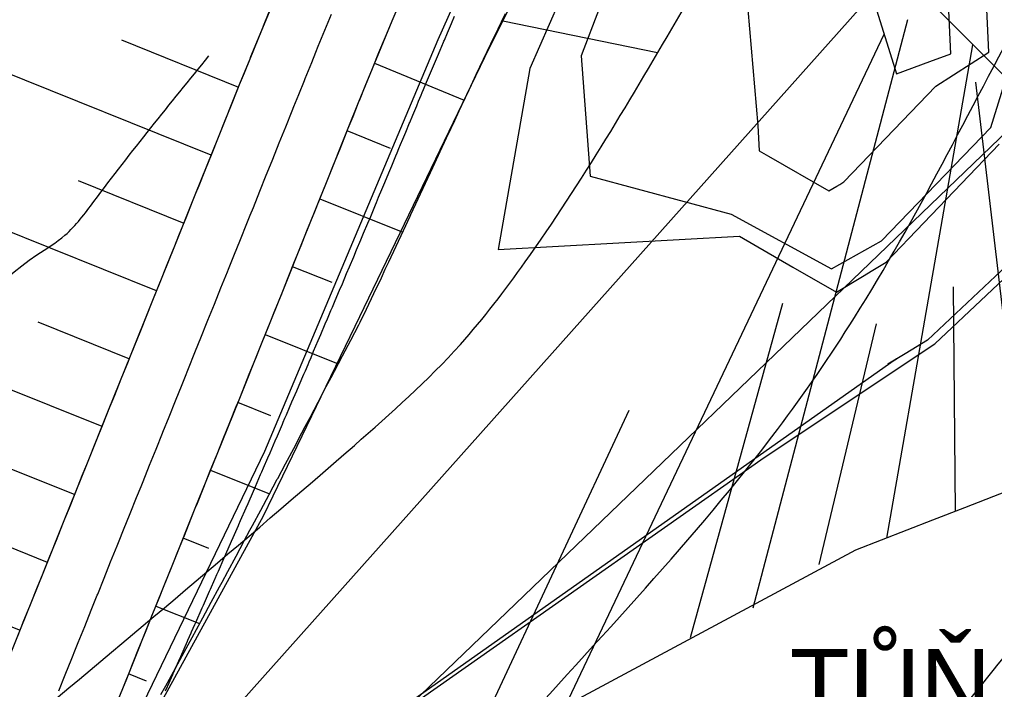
# Model space of a CAD drawing. Extents: x -564091 to -563943, y -1163604 to -1163394.
# Drawn here: x -563977.47 to -563960.81, y -1163497.05 to -1163485.61 of the extents above; entities that cross this region are included whole.
import ezdxf

# ---------------------------------------------------------------- set-up
doc = ezdxf.new("R2010")
doc.units = 0
for name, color, linetype in [('4', 7, 'Continuous'), ('5', 7, 'Continuous'), ('Default', 7, 'Continuous'), ('Line', 7, 'Continuous'), ('Vrstva 24', 7, 'Continuous'), ('Vrstva 25', 7, 'Continuous'), ('Vrstva 26', 7, 'Continuous')]:
    doc.layers.add(name, color=color, linetype=linetype)

msp = doc.modelspace()

# ---------------------------------------------------------------- linework, layer by layer
for points in [[(-563976.663, -1163501.462), (-563964.742, -1163493.091), (-563961.829, -1163491.15), (-563957.41, -1163486.988), (-563956.735, -1163486.627), (-563953.281, -1163481.221), (-563953.993, -1163478.343), (-563957.796, -1163470.824), (-563957.81, -1163470.439), (-563957.835, -1163469.754), (-563958.239, -1163469.063), (-563958.187, -1163468.683), (-563959.529, -1163466.077), (-563960.166, -1163464.984), (-563964.31, -1163473.527), (-563966.903, -1163478.544), (-563968.406, -1163481.669), (-563970.316, -1163485.955), (-563973.278, -1163492.988), (-563976.735, -1163500.155), (-563977.161, -1163500.889), (-563977.363, -1163501.307)], [(-563962.125, -1163475.875), (-563962.765, -1163475.108), (-563963.856, -1163475.351), (-563965.212, -1163477.785), (-563966.919, -1163483.486), (-563967.557, -1163485.407), (-563967.871, -1163486.226), (-563967.716, -1163488.285), (-563965.306, -1163488.933), (-563963.594, -1163489.868), (-563962.736, -1163489.387), (-563960.869, -1163487.453), (-563959.333, -1163482.497), (-563959.613, -1163479.666)], [(-563962.48, -1163486.536), (-563961.911, -1163486.326), (-563961.553, -1163486.194), (-563961.747, -1163482.024), (-563961.878, -1163479.201), (-563962.246, -1163479.103), (-563962.794, -1163479.244), (-563962.818, -1163479.245), (-563963.128, -1163481.546), (-563962.901, -1163485.181)]]:
    msp.add_lwpolyline(points, close=True)
for points in [[(-563960.523, -1163486.688), (-563961.829, -1163485.385), (-563962.324, -1163483.708), (-563962.461, -1163482.584), (-563962.597, -1163481.459), (-563962.579, -1163480.501), (-563961.736, -1163479.195), (-563961.088, -1163479.165), (-563960.669, -1163479.145), (-563960.089, -1163479.118), (-563959.09, -1163479.072), (-563958.091, -1163479.026), (-563957.266, -1163478.987), (-563957.092, -1163478.979), (-563955.995, -1163480.274), (-563955.699, -1163482.25), (-563955.954, -1163483.392), (-563956.177, -1163485.128), (-563956.177, -1163485.128), (-563956.177, -1163485.128), (-563957.55, -1163486.21)], [(-563965.051, -1163485.101), (-563964.85, -1163487.418), (-563964.83, -1163487.847), (-563964.668, -1163487.941), (-563963.636, -1163488.535), (-563963.502, -1163488.454), (-563963.449, -1163488.423), (-563963.381, -1163488.382), (-563961.809, -1163486.742), (-563960.902, -1163486.164), (-563961.157, -1163480.663)], [(-563960.591, -1163493.664), (-563961.319, -1163493.948), (-563961.866, -1163494.161), (-563963.182, -1163494.674), (-563968.138, -1163497.33), (-563968.634, -1163497.596), (-563970.944, -1163498.688), (-563971.597, -1163498.997), (-563976.56, -1163501.343), (-563977.332, -1163501.295), (-563976.988, -1163500.693), (-563975.559, -1163498.192), (-563975.396, -1163497.906), (-563973.296, -1163494.084), (-563973.133, -1163493.747), (-563971.654, -1163490.682), (-563969.513, -1163486.248), (-563968.702, -1163484.611)], [(-563977.812, -1163496.922), (-563977.438, -1163495.994), (-563977.065, -1163495.066), (-563976.691, -1163494.139), (-563976.318, -1163493.211), (-563975.945, -1163492.283), (-563975.571, -1163491.355), (-563975.198, -1163490.428), (-563974.825, -1163489.5), (-563974.451, -1163488.572), (-563974.078, -1163487.645), (-563973.705, -1163486.717), (-563973.527, -1163486.276), (-563973.328, -1163485.785), (-563972.941, -1163484.852)], [(-563977.421, -1163501.309), (-563977.076, -1163500.451), (-563977.017, -1163500.304), (-563976.703, -1163499.524), (-563976.33, -1163498.596), (-563975.956, -1163497.668), (-563975.583, -1163496.741), (-563975.209, -1163495.813), (-563974.836, -1163494.885), (-563974.463, -1163493.958), (-563974.089, -1163493.03), (-563973.716, -1163492.102), (-563973.343, -1163491.175), (-563972.969, -1163490.247), (-563972.596, -1163489.319), (-563972.223, -1163488.391), (-563971.849, -1163487.464), (-563971.672, -1163487.023), (-563971.476, -1163486.542), (-563971.097, -1163485.627), (-563970.817, -1163484.966)], [(-563968.084, -1163484.934), (-563968.744, -1163486.445), (-563969.289, -1163489.534), (-563965.164, -1163489.309), (-563965.164, -1163489.309), (-563964.25, -1163489.835), (-563963.508, -1163490.263), (-563963.061, -1163489.994), (-563962.883, -1163489.889), (-563962.657, -1163489.751), (-563960.727, -1163487.738)], [(-563977.502, -1163496.152), (-563977.438, -1163495.994), (-563977.391, -1163495.877), (-563977.28, -1163495.601), (-563977.169, -1163495.326), (-563977.065, -1163495.066), (-563977.059, -1163495.051), (-563976.948, -1163494.775), (-563976.837, -1163494.5), (-563976.726, -1163494.225), (-563976.691, -1163494.139), (-563976.615, -1163493.949), (-563976.505, -1163493.674), (-563976.394, -1163493.399), (-563976.318, -1163493.211), (-563976.283, -1163493.123), (-563976.172, -1163492.848), (-563976.061, -1163492.573), (-563975.95, -1163492.297), (-563975.945, -1163492.283), (-563975.84, -1163492.022), (-563975.729, -1163491.747), (-563975.618, -1163491.471), (-563975.571, -1163491.355), (-563975.507, -1163491.196), (-563975.396, -1163490.921), (-563975.286, -1163490.645), (-563975.198, -1163490.428), (-563975.175, -1163490.37), (-563975.064, -1163490.095), (-563974.953, -1163489.819), (-563974.842, -1163489.544), (-563974.825, -1163489.5), (-563974.732, -1163489.269), (-563974.621, -1163488.994), (-563974.51, -1163488.718), (-563974.451, -1163488.572), (-563974.399, -1163488.443), (-563974.288, -1163488.168), (-563974.177, -1163487.892), (-563974.078, -1163487.645), (-563974.067, -1163487.617), (-563973.956, -1163487.342), (-563973.845, -1163487.066), (-563973.734, -1163486.791), (-563973.705, -1163486.717), (-563973.623, -1163486.516), (-563973.527, -1163486.276), (-563973.512, -1163486.24), (-563973.4, -1163485.962), (-563973.328, -1163485.785), (-563973.287, -1163485.685), (-563973.173, -1163485.407)], [(-563975.757, -1163497.174), (-563975.646, -1163496.899), (-563975.583, -1163496.741), (-563975.536, -1163496.623), (-563975.425, -1163496.348), (-563975.314, -1163496.073), (-563975.209, -1163495.813), (-563975.203, -1163495.797), (-563975.092, -1163495.522), (-563974.982, -1163495.247), (-563974.871, -1163494.971), (-563974.836, -1163494.885), (-563974.76, -1163494.696), (-563974.649, -1163494.421), (-563974.538, -1163494.145), (-563974.463, -1163493.958), (-563974.428, -1163493.87), (-563974.317, -1163493.595), (-563974.206, -1163493.319), (-563974.095, -1163493.044), (-563974.089, -1163493.03), (-563973.984, -1163492.769), (-563973.873, -1163492.493), (-563973.763, -1163492.218), (-563973.716, -1163492.102), (-563973.652, -1163491.943), (-563973.541, -1163491.668), (-563973.43, -1163491.392), (-563973.343, -1163491.175), (-563973.319, -1163491.117), (-563973.209, -1163490.842), (-563973.098, -1163490.566), (-563972.987, -1163490.291), (-563972.969, -1163490.247), (-563972.876, -1163490.016), (-563972.765, -1163489.74), (-563972.655, -1163489.465), (-563972.596, -1163489.319), (-563972.544, -1163489.19), (-563972.433, -1163488.914), (-563972.322, -1163488.639), (-563972.223, -1163488.391), (-563972.211, -1163488.364), (-563972.101, -1163488.088), (-563971.99, -1163487.813), (-563971.879, -1163487.538), (-563971.849, -1163487.464), (-563971.768, -1163487.262), (-563971.672, -1163487.023), (-563971.657, -1163486.987), (-563971.547, -1163486.715), (-563971.476, -1163486.542), (-563971.436, -1163486.443), (-563971.324, -1163486.171), (-563971.212, -1163485.9), (-563971.098, -1163485.629), (-563971.097, -1163485.627), (-563970.984, -1163485.358)], [(-563976.796, -1163497.076), (-563976.685, -1163496.801), (-563976.574, -1163496.525), (-563976.511, -1163496.367), (-563976.463, -1163496.25), (-563976.353, -1163495.975), (-563976.242, -1163495.699), (-563976.137, -1163495.44), (-563976.131, -1163495.424), (-563976.02, -1163495.149), (-563975.909, -1163494.873), (-563975.798, -1163494.598), (-563975.764, -1163494.512), (-563975.688, -1163494.323), (-563975.577, -1163494.047), (-563975.466, -1163493.772), (-563975.39, -1163493.584), (-563975.355, -1163493.497), (-563975.244, -1163493.221), (-563975.134, -1163492.946), (-563975.023, -1163492.671), (-563975.017, -1163492.657), (-563974.912, -1163492.395), (-563974.801, -1163492.12), (-563974.69, -1163491.845), (-563974.644, -1163491.729), (-563974.58, -1163491.569), (-563974.469, -1163491.294), (-563974.358, -1163491.019), (-563974.27, -1163490.801), (-563974.247, -1163490.744), (-563974.136, -1163490.468), (-563974.025, -1163490.193), (-563973.915, -1163489.918), (-563973.897, -1163489.873), (-563973.804, -1163489.642), (-563973.693, -1163489.367), (-563973.582, -1163489.092), (-563973.524, -1163488.946), (-563973.471, -1163488.816), (-563973.361, -1163488.541), (-563973.25, -1163488.266), (-563973.15, -1163488.018), (-563973.139, -1163487.99), (-563973.028, -1163487.715), (-563972.917, -1163487.44), (-563972.807, -1163487.164), (-563972.777, -1163487.09), (-563972.696, -1163486.889), (-563972.599, -1163486.649), (-563972.585, -1163486.614), (-563972.474, -1163486.339), (-563972.402, -1163486.163), (-563972.361, -1163486.064), (-563972.249, -1163485.789), (-563972.135, -1163485.515)], [(-563975.049, -1163497.139), (-563974.967, -1163496.989), (-563974.906, -1163496.877), (-563974.763, -1163496.614), (-563974.62, -1163496.352), (-563974.485, -1163496.104), (-563974.477, -1163496.09), (-563974.335, -1163495.827), (-563974.192, -1163495.564), (-563974.05, -1163495.302), (-563974.006, -1163495.219), (-563973.909, -1163495.039), (-563973.767, -1163494.776), (-563973.625, -1163494.513), (-563973.529, -1163494.333), (-563973.484, -1163494.25), (-563973.343, -1163493.987), (-563973.202, -1163493.723), (-563973.062, -1163493.46), (-563973.055, -1163493.446), (-563972.922, -1163493.196), (-563972.782, -1163492.933), (-563972.642, -1163492.669), (-563972.583, -1163492.558), (-563972.502, -1163492.405), (-563972.363, -1163492.142), (-563972.224, -1163491.878), (-563972.114, -1163491.669), (-563972.085, -1163491.614), (-563971.946, -1163491.35), (-563971.808, -1163491.085), (-563971.669, -1163490.821), (-563971.647, -1163490.779), (-563971.537, -1163490.555), (-563971.41, -1163490.286), (-563971.283, -1163490.017), (-563971.216, -1163489.874), (-563971.157, -1163489.748), (-563971.03, -1163489.479), (-563970.904, -1163489.21), (-563970.791, -1163488.968), (-563970.778, -1163488.94), (-563970.653, -1163488.671), (-563970.527, -1163488.402), (-563970.402, -1163488.132), (-563970.368, -1163488.06), (-563970.277, -1163487.863), (-563970.168, -1163487.628), (-563970.152, -1163487.594), (-563970.03, -1163487.332), (-563969.952, -1163487.164), (-563969.908, -1163487.069), (-563969.785, -1163486.808), (-563969.662, -1163486.546), (-563969.538, -1163486.285), (-563969.537, -1163486.283), (-563969.414, -1163486.024), (-563969.289, -1163485.763), (-563969.233, -1163485.646), (-563969.164, -1163485.502)], [(-563975.049, -1163497.139), (-563974.967, -1163496.989), (-563974.906, -1163496.877), (-563974.763, -1163496.614), (-563974.62, -1163496.352), (-563974.485, -1163496.104), (-563974.477, -1163496.09), (-563974.335, -1163495.827), (-563974.192, -1163495.564), (-563974.05, -1163495.302), (-563974.006, -1163495.219), (-563973.909, -1163495.039), (-563973.767, -1163494.776), (-563973.625, -1163494.513), (-563973.529, -1163494.333), (-563973.484, -1163494.25), (-563973.343, -1163493.987), (-563973.202, -1163493.723), (-563973.062, -1163493.46), (-563973.055, -1163493.446), (-563972.922, -1163493.196), (-563972.782, -1163492.933), (-563972.642, -1163492.669), (-563972.583, -1163492.558), (-563972.502, -1163492.405), (-563972.363, -1163492.142), (-563972.224, -1163491.878), (-563972.114, -1163491.669), (-563972.085, -1163491.614), (-563971.946, -1163491.35), (-563971.808, -1163491.085), (-563971.669, -1163490.821), (-563971.647, -1163490.779), (-563971.537, -1163490.555), (-563971.41, -1163490.286), (-563971.283, -1163490.017), (-563971.216, -1163489.874), (-563971.157, -1163489.748), (-563971.03, -1163489.479), (-563970.904, -1163489.21), (-563970.791, -1163488.968), (-563970.778, -1163488.94), (-563970.653, -1163488.671), (-563970.527, -1163488.402), (-563970.402, -1163488.132), (-563970.368, -1163488.06), (-563970.277, -1163487.863), (-563970.168, -1163487.628), (-563970.152, -1163487.594), (-563970.03, -1163487.332), (-563969.952, -1163487.164), (-563969.908, -1163487.069), (-563969.785, -1163486.808), (-563969.662, -1163486.546), (-563969.538, -1163486.285), (-563969.537, -1163486.283), (-563969.414, -1163486.024), (-563969.289, -1163485.763), (-563969.233, -1163485.646), (-563969.164, -1163485.502)]]:
    msp.add_lwpolyline(points)
at = {"layer": '5'}
msp.add_line((-563974.94, -1163501.303), (-563959.546, -1163486.507), dxfattribs=at)
at = {"layer": 'Default'}
for points in [[(-563974.974, -1163497.079), (-563974.939, -1163497), (-563974.935, -1163496.992), (-563974.849, -1163496.797), (-563974.841, -1163496.78), (-563974.722, -1163496.513), (-563974.711, -1163496.488), (-563974.596, -1163496.229), (-563974.589, -1163496.212), (-563974.532, -1163496.085), (-563974.525, -1163496.068), (-563974.47, -1163495.944), (-563974.453, -1163495.906), (-563974.344, -1163495.659), (-563974.324, -1163495.615), (-563974.218, -1163495.374), (-563974.203, -1163495.339), (-563974.128, -1163495.17), (-563974.122, -1163495.155), (-563974.093, -1163495.09), (-563974.069, -1163495.034), (-563973.968, -1163494.805), (-563973.941, -1163494.744), (-563973.843, -1163494.52), (-563973.816, -1163494.459), (-563973.727, -1163494.254), (-563973.725, -1163494.249), (-563973.718, -1163494.234), (-563973.688, -1163494.165), (-563973.594, -1163493.949), (-563973.562, -1163493.876), (-563973.47, -1163493.664), (-563973.436, -1163493.586), (-563973.346, -1163493.378), (-563973.341, -1163493.366), (-563973.328, -1163493.337), (-563973.297, -1163493.267), (-563973.222, -1163493.093), (-563973.185, -1163493.008), (-563973.099, -1163492.807), (-563973.061, -1163492.719), (-563972.975, -1163492.522), (-563972.961, -1163492.488), (-563972.931, -1163492.418), (-563972.905, -1163492.359), (-563972.852, -1163492.236), (-563972.812, -1163492.141), (-563972.729, -1163491.95), (-563972.688, -1163491.852), (-563972.607, -1163491.664), (-563972.582, -1163491.606), (-563972.536, -1163491.499), (-563972.518, -1163491.456), (-563972.485, -1163491.378), (-563972.441, -1163491.275), (-563972.363, -1163491.092), (-563972.318, -1163490.986), (-563972.241, -1163490.805), (-563972.204, -1163490.719), (-563972.145, -1163490.579), (-563972.135, -1163490.556), (-563972.119, -1163490.519), (-563972.072, -1163490.408), (-563971.998, -1163490.232), (-563971.95, -1163490.12), (-563971.877, -1163489.946), (-563971.829, -1163489.833), (-563971.756, -1163489.659), (-563971.756, -1163489.659), (-563971.755, -1163489.658), (-563971.707, -1163489.544), (-563971.635, -1163489.372), (-563971.587, -1163489.257), (-563971.515, -1163489.086), (-563971.466, -1163488.969), (-563971.395, -1163488.799), (-563971.384, -1163488.773), (-563971.368, -1163488.735), (-563971.33, -1163488.644), (-563971.275, -1163488.512), (-563971.225, -1163488.393), (-563971.155, -1163488.224), (-563971.105, -1163488.105), (-563971.036, -1163487.937), (-563971.014, -1163487.885), (-563970.984, -1163487.812), (-563970.955, -1163487.744), (-563970.916, -1163487.65), (-563970.868, -1163487.533), (-563970.802, -1163487.373), (-563970.8, -1163487.368), (-563970.797, -1163487.363), (-563970.747, -1163487.242), (-563970.68, -1163487.081), (-563970.647, -1163487.002), (-563970.604, -1163486.898), (-563970.586, -1163486.855), (-563970.563, -1163486.799), (-563970.511, -1163486.677), (-563970.445, -1163486.518), (-563970.392, -1163486.395), (-563970.326, -1163486.237), (-563970.28, -1163486.13), (-563970.222, -1163485.995), (-563970.215, -1163485.978), (-563970.206, -1163485.957), (-563970.153, -1163485.832), (-563970.086, -1163485.676), (-563970.032, -1163485.551)], [(-563957.497, -1163486.891), (-563961.953, -1163491.085), (-563962.333, -1163491.316), (-563962.631, -1163491.492), (-563962.482, -1163491.404), (-563976.56, -1163501.343)]]:
    msp.add_lwpolyline(points, dxfattribs=at)
at = {"layer": 'Line'}
for p, q in [((-563962.901, -1163485.181), (-563977.279, -1163501.298)), ((-563966.564, -1163486.174), (-563969.208, -1163485.632)), ((-563964.928, -1163495.656), (-563962.285, -1163485.606)), ((-563975.726, -1163485.954), (-563973.723, -1163486.764)), ((-563968.138, -1163497.33), (-563962.69, -1163485.858)), ((-563962.645, -1163494.465), (-563961.176, -1163486.037)), ((-563974.19, -1163487.923), (-563977.994, -1163486.392)), ((-563971.398, -1163486.352), (-563969.867, -1163486.983)), ((-563960.316, -1163493.557), (-563961.127, -1163486.674)), ((-563971.129, -1163487.809), (-563971.868, -1163487.51)), ((-563976.466, -1163488.355), (-563974.657, -1163489.083)), ((-563972.335, -1163488.67), (-563970.918, -1163489.24)), ((-563975.123, -1163490.242), (-563978.542, -1163488.867)), ((-563972.126, -1163490.101), (-563972.801, -1163489.829)), ((-563961.513, -1163490.172), (-563961.48, -1163494.011)), ((-563964.431, -1163490.456), (-563966.005, -1163496.172)), ((-563977.155, -1163490.772), (-563975.59, -1163491.402)), ((-563962.83, -1163490.808), (-563963.81, -1163494.918)), ((-563973.268, -1163490.989), (-563972.021, -1163491.491)), ((-563976.057, -1163492.562), (-563978.885, -1163491.423)), ((-563973.171, -1163492.376), (-563973.735, -1163492.149)), ((-563967.053, -1163492.285), (-563969.789, -1163498.142)), ((-563977.783, -1163493.214), (-563976.523, -1163493.721)), ((-563974.201, -1163493.308), (-563973.196, -1163493.713)), ((-563976.99, -1163494.881), (-563979.193, -1163493.994)), ((-563974.23, -1163494.644), (-563974.668, -1163494.468)), ((-563975.135, -1163495.627), (-563974.389, -1163495.928)), ((-563978.396, -1163495.662), (-563977.457, -1163496.04)), ((-563975.296, -1163496.91), (-563975.602, -1163496.787))]:
    msp.add_line(p, q, dxfattribs=at)
at = {"layer": 'Vrstva 24'}
for points in [[(-563987.107, -1163486.915), (-563987.454, -1163489.613), (-563987.517, -1163490.15), (-563987.54, -1163490.422), (-563987.53, -1163490.559), (-563987.493, -1163490.695), (-563987.417, -1163490.784), (-563987.298, -1163490.832), (-563987.065, -1163490.801), (-563986.897, -1163490.636), (-563986.866, -1163490.616), (-563986.653, -1163490.561), (-563986.65, -1163490.24), (-563986.645, -1163490.2), (-563986.382, -1163489.381), (-563986.092, -1163488.576), (-563985.799, -1163487.775), (-563985.528, -1163486.967), (-563985.38, -1163486.476), (-563984.961, -1163484.997), (-563984.678, -1163484.011), (-563984.372, -1163483.032), (-563984.225, -1163482.649), (-563983.962, -1163482.075), (-563983.672, -1163481.512), (-563983.189, -1163480.348), (-563983.119, -1163479.959), (-563982.881, -1163478.598), (-563982.738, -1163477.921), (-563982.65, -1163477.583), (-563982.6, -1163477.415), (-563982.546, -1163477.247), (-563982.332, -1163477.109), (-563982.215, -1163477.074), (-563982.092, -1163477.059), (-563981.971, -1163477.035), (-563981.858, -1163476.974), (-563981.222, -1163476.317), (-563980.763, -1163475.576), (-563980.303, -1163473.933), (-563980.283, -1163473.505), (-563980.299, -1163473.076), (-563980.318, -1163472.648), (-563980.308, -1163472.221), (-563980.208, -1163471.241), (-563979.978, -1163470.27), (-563979.506, -1163469.655), (-563979.053, -1163469.383), (-563978.331, -1163469.068), (-563977.756, -1163469.029), (-563977.053, -1163469.053), (-563976.495, -1163468.977), (-563976.227, -1163468.861), (-563976.095, -1163468.775), (-563975.963, -1163468.666), (-563975.645, -1163468.239), (-563975.569, -1163468.015), (-563975.54, -1163467.788), (-563975.712, -1163467.263), (-563975.92, -1163467.014), (-563976.134, -1163466.799), (-563976.603, -1163466.431), (-563977.767, -1163465.694), (-563978.114, -1163465.416), (-563978.319, -1163465.046), (-563978.354, -1163464.593), (-563978.366, -1163464.139), (-563978.374, -1163463.685), (-563978.396, -1163463.232), (-563978.403, -1163463.165), (-563978.508, -1163462.771), (-563978.665, -1163462.394), (-563979.088, -1163461.691), (-563979.473, -1163461.171), (-563980.119, -1163460.346)], [(-563978.297, -1163509.021), (-563978.261, -1163509.003), (-563973.613, -1163506.565), (-563973.263, -1163506.351), (-563972.852, -1163506.074), (-563964.784, -1163500.778), (-563963.064, -1163499.262), (-563960.133, -1163495.845), (-563958.857, -1163494.133), (-563956.661, -1163490.461), (-563954.703, -1163486.917), (-563951.017, -1163480.396), (-563950.659, -1163479.782), (-563950.563, -1163479.619)], [(-563978.949, -1163516.619), (-563975.171, -1163515.313), (-563974.108, -1163514.884), (-563972.002, -1163513.885), (-563969.907, -1163512.865), (-563967.813, -1163511.846), (-563965.709, -1163510.847), (-563964.325, -1163510.207), (-563962.597, -1163509.381), (-563961.075, -1163508.613), (-563959.57, -1163507.812), (-563958.075, -1163506.99), (-563956.583, -1163506.159), (-563955.558, -1163505.578), (-563954.547, -1163504.976), (-563953.555, -1163504.342), (-563952.588, -1163503.665), (-563951.319, -1163502.66), (-563950.112, -1163501.587), (-563949.038, -1163500.583), (-563947.98, -1163499.563), (-563946.918, -1163498.547), (-563945.835, -1163497.554), (-563945.703, -1163497.443), (-563945.609, -1163497.371), (-563945.171, -1163496.955), (-563943.72, -1163495.5)]]:
    msp.add_spline(points, degree=3, dxfattribs=at)
at = {"layer": 'Vrstva 25'}
msp.add_spline([(-563979.181, -1163499.008), (-563978.428, -1163498.506), (-563977.533, -1163497.79), (-563971.745, -1163492.882), (-563969.933, -1163491.157), (-563968.824, -1163489.747), (-563966.163, -1163485.494), (-563965.399, -1163484.181), (-563964.1, -1163481.868), (-563961.431, -1163477.021), (-563960.731, -1163475.725), (-563960.044, -1163474.189), (-563959.617, -1163472.641), (-563959.116, -1163469.866), (-563959.228, -1163469.046), (-563959.512, -1163468.326), (-563959.82, -1163467.638), (-563960.515, -1163466.313), (-563961.208, -1163465.1)], degree=3, dxfattribs=at)
at = {"layer": 'Vrstva 26'}
for points in [[(-563980.746, -1163506.255), (-563980.047, -1163505.928), (-563978.898, -1163505.186), (-563978.091, -1163504.559), (-563977.304, -1163503.908), (-563976.514, -1163503.264), (-563975.695, -1163502.656), (-563974.591, -1163501.929), (-563973.468, -1163501.232), (-563972.341, -1163500.538), (-563971.226, -1163499.825), (-563970.447, -1163499.268), (-563969.15, -1163497.951), (-563964.517, -1163492.611), (-563963.2, -1163490.7), (-563960.284, -1163485.41), (-563958.779, -1163482.786), (-563956.142, -1163478.307), (-563954.428, -1163475.228)], [(-564001.195, -1163498.271), (-563999.625, -1163497.54), (-563999.32, -1163497.49), (-563999.014, -1163497.455), (-563998.404, -1163497.374), (-563997.456, -1163497.19), (-563996.983, -1163497.106), (-563996.746, -1163497.08), (-563996.628, -1163497.073), (-563996.51, -1163497.07), (-563996.001, -1163497.405), (-563995.843, -1163497.69), (-563995.811, -1163497.929), (-563995.865, -1163498.008), (-563995.966, -1163498.084), (-563996.177, -1163498.245), (-563996.314, -1163498.396), (-563996.473, -1163498.559), (-563996.786, -1163498.911), (-563996.954, -1163499.618), (-563996.725, -1163499.926), (-563996.435, -1163500.208), (-563996.113, -1163500.428), (-563995.791, -1163500.55), (-563995.579, -1163500.527), (-563995.362, -1163500.405), (-563995.147, -1163500.225), (-563994.94, -1163500.032), (-563994.454, -1163499.316), (-563994.189, -1163498.497), (-563993.911, -1163497.703), (-563993.694, -1163497.356), (-563993.385, -1163497.063), (-563993.106, -1163496.925), (-563992.801, -1163496.863), (-563992.211, -1163496.877), (-563991.901, -1163497.039), (-563991.591, -1163497.33), (-563991.287, -1163497.564), (-563990.995, -1163497.556), (-563990.269, -1163497.037), (-563989.554, -1163496.504), (-563988.84, -1163495.969), (-563988.119, -1163495.444), (-563987.86, -1163495.24), (-563987.725, -1163495.146), (-563987.573, -1163495.071), (-563987.369, -1163495.063), (-563987.165, -1163495.092), (-563986.561, -1163495.087), (-563985.951, -1163495.108), (-563984.727, -1163495.135), (-563983.531, -1163494.982), (-563982.954, -1163494.778), (-563982.673, -1163494.634), (-563982.398, -1163494.458), (-563981.989, -1163494.127), (-563981.638, -1163493.78), (-563980.962, -1163493.086), (-563979.072, -1163491.35), (-563977.168, -1163489.628), (-563976.69, -1163489.292), (-563976.196, -1163488.717), (-563974.229, -1163486.225)], [(-563979.339, -1163513.451), (-563976.454, -1163512.115), (-563974.079, -1163510.944), (-563968.189, -1163507.943), (-563964.488, -1163505.88), (-563958.479, -1163502.145), (-563957, -1163500.857), (-563954.437, -1163497.718), (-563953.277, -1163496.363), (-563952.789, -1163495.73), (-563951.998, -1163494.583), (-563951.243, -1163493.409), (-563950.48, -1163492.242), (-563949.665, -1163491.113), (-563947.525, -1163488.408), (-563947.448, -1163488.312)]]:
    msp.add_spline(points, degree=3, dxfattribs=at)

# ---------------------------------------------------------------- texts
at = {"layer": '4'}
msp.add_text('TŮŇ T1', height=1.25, rotation=360, dxfattribs=at).set_placement((-563964.304, -1163497.609))

doc.saveas('drawing.dxf')
